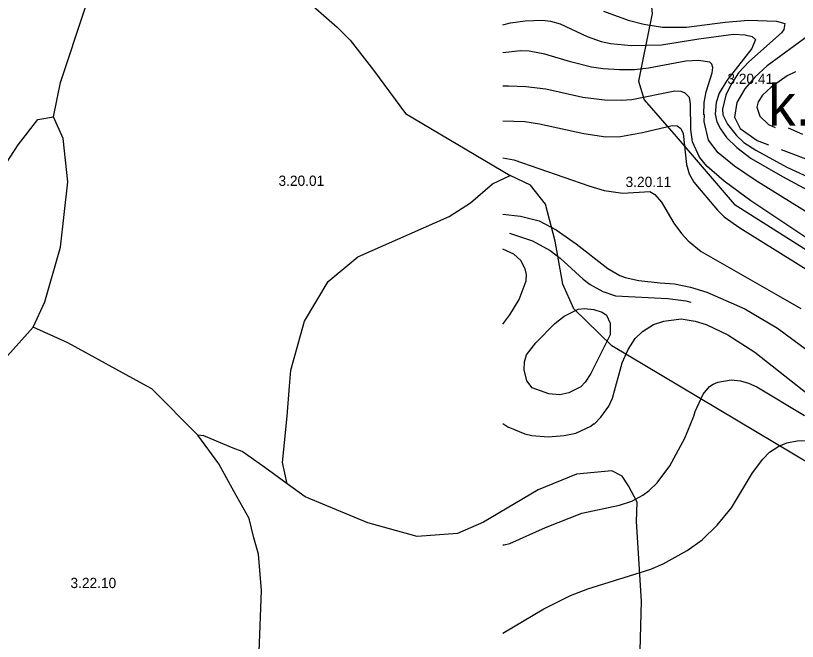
# Model space of a CAD drawing. Extents: x -662500 to -653478, y -1056827 to -1049993.
# Drawn here: x -661949 to -661377, y -1052187 to -1051729 of the extents above; entities that cross this region are included whole.
import ezdxf

# ---------------------------------------------------------------- set-up
doc = ezdxf.new("R2010")
doc.units = 0
for name, color, linetype in [('58', 7, 'Continuous'), ('Vrstva 24', 7, 'Continuous'), ('Vrstva 7', 7, 'Continuous')]:
    doc.layers.add(name, color=color, linetype=linetype)

msp = doc.modelspace()

# ---------------------------------------------------------------- linework, layer by layer
at = {"layer": 'Vrstva 24'}
for points in [[(-661490, -1051648), (-661487.5, -1051669), (-661486.5, -1051694), (-661483, -1051727.5), (-661490.5, -1051763.5), (-661493, -1051777), (-661489, -1051790.5), (-661465.5, -1051817.5), (-661423, -1051867), (-661344, -1051917)], [(-661921, -1051803), (-661916, -1051778), (-661898, -1051723.5), (-661882, -1051673)], [(-661882, -1051673), (-661865.5, -1051680), (-661808.5, -1051691), (-661771.5, -1051702.5), (-661762, -1051705), (-661744, -1051714.5), (-661731, -1051722), (-661713.5, -1051737.5), (-661704, -1051747), (-661687, -1051769), (-661663.5, -1051800.5), (-661587, -1051846)], [(-662096, -1051971), (-662093, -1051958.5), (-662081.5, -1051931.5), (-662066.5, -1051913.5), (-661997.5, -1051871.5), (-661971, -1051851), (-661958.5, -1051841.5), (-661947, -1051823.5), (-661932.5, -1051805), (-661921, -1051803)], [(-661936, -1051957), (-661927.5, -1051938.5), (-661916, -1051898.5), (-661910.5, -1051850.5), (-661914, -1051819), (-661921, -1051803)], [(-661750, -1052071.5), (-661753.5, -1052056), (-661750, -1052022), (-661748.36, -1052000), (-661747.5, -1051988.5), (-661737.5, -1051952.5), (-661720, -1051923.5), (-661698.5, -1051905.5), (-661631.5, -1051876), (-661616, -1051866), (-661600, -1051852), (-661587, -1051846)], [(-661191, -1052048), (-661295, -1052071.5), (-661327.5, -1052073.5), (-661352, -1052066.5), (-661463.18, -1052000), (-661512.5, -1051970.5), (-661540.5, -1051943.5), (-661548.5, -1051925.5), (-661554, -1051894), (-661561, -1051867), (-661572, -1051853), (-661587, -1051846)], [(-661794, -1052312.5), (-661840, -1052307.5), (-661898, -1052305.5), (-661929.5, -1052300.5), (-661957, -1052291.5), (-661974.5, -1052281), (-662001, -1052255), (-662045.5, -1052192), (-662051, -1052169.5), (-662044.5, -1052124.5), (-662027, -1052066), (-662005.5, -1052025.5), (-661977.17, -1052000), (-661965.5, -1051989.5), (-661936, -1051957)], [(-661815.5, -1052036), (-661849, -1052002), (-661852.67, -1052000), (-661910.5, -1051968.5), (-661936, -1051957)], [(-661794, -1052312.5), (-661770.5, -1052194.5), (-661769, -1052149.5), (-661771, -1052123), (-661774.5, -1052111), (-661778, -1052097), (-661789, -1052077.5), (-661800, -1052057), (-661815.5, -1052036)], [(-661750, -1052071.5), (-661766.5, -1052059.5), (-661783, -1052048), (-661789.5, -1052045.5), (-661811, -1052036.5), (-661815.5, -1052036)], [(-661493, -1052317.5), (-661495, -1052310.5), (-661491, -1052157.5), (-661494.5, -1052099), (-661494, -1052085), (-661500.5, -1052073), (-661505, -1052066), (-661512.5, -1052062), (-661538.5, -1052064.5), (-661566.5, -1052076), (-661606.5, -1052099.5), (-661625.5, -1052108), (-661655, -1052110), (-661691, -1052100), (-661737, -1052081), (-661750, -1052071.5)]]:
    msp.add_lwpolyline(points, dxfattribs=at)
at = {"layer": 'Vrstva 7'}
for p, q in [((-661518.72, -1051725.73), (-661500.58, -1051732.39)), ((-661518.72, -1051725.73), (-661500.58, -1051732.39)), ((-661592.25, -1051735.65), (-661586.74, -1051734.38)), ((-661592.25, -1051735.65), (-661586.74, -1051734.38)), ((-661586.74, -1051734.38), (-661575.97, -1051732.82)), ((-661586.74, -1051734.38), (-661575.97, -1051732.82)), ((-661575.97, -1051732.82), (-661563.22, -1051732.25)), ((-661575.97, -1051732.82), (-661563.22, -1051732.25)), ((-661563.22, -1051732.25), (-661557.55, -1051732.96)), ((-661563.22, -1051732.25), (-661557.55, -1051732.96)), ((-661557.55, -1051732.96), (-661550.46, -1051735.08)), ((-661557.55, -1051732.96), (-661550.46, -1051735.08)), ((-661550.46, -1051735.08), (-661530.62, -1051744.3)), ((-661550.46, -1051735.08), (-661530.62, -1051744.3)), ((-661500.58, -1051732.39), (-661489.24, -1051735.23)), ((-661500.58, -1051732.39), (-661489.24, -1051735.23)), ((-661489.24, -1051735.23), (-661475.64, -1051737.35)), ((-661489.24, -1051735.23), (-661475.64, -1051737.35)), ((-661458.07, -1051737.35), (-661429.72, -1051733.67)), ((-661458.07, -1051737.35), (-661429.72, -1051733.67)), ((-661429.72, -1051733.67), (-661412.72, -1051732.39)), ((-661429.72, -1051733.67), (-661412.72, -1051732.39)), ((-661412.72, -1051732.39), (-661392.03, -1051733.1)), ((-661412.72, -1051732.39), (-661392.03, -1051733.1)), ((-661392.03, -1051733.1), (-661385.93, -1051734.66)), ((-661392.03, -1051733.1), (-661385.93, -1051734.66)), ((-661385.93, -1051734.66), (-661386.78, -1051739.05)), ((-661385.93, -1051734.66), (-661386.78, -1051739.05)), ((-661475.64, -1051737.35), (-661458.07, -1051737.35)), ((-661475.64, -1051737.35), (-661458.07, -1051737.35)), ((-661448.99, -1051745.85), (-661423.49, -1051742.6)), ((-661448.99, -1051745.85), (-661423.49, -1051742.6)), ((-661423.49, -1051742.6), (-661414.98, -1051743.02)), ((-661423.49, -1051742.6), (-661414.98, -1051743.02)), ((-661388.48, -1051741.46), (-661412.43, -1051762.72)), ((-661388.48, -1051741.46), (-661412.43, -1051762.72)), ((-661386.78, -1051739.05), (-661388.48, -1051741.46)), ((-661386.78, -1051739.05), (-661388.48, -1051741.46)), ((-661530.62, -1051744.3), (-661520.42, -1051747.84)), ((-661530.62, -1051744.3), (-661520.42, -1051747.84)), ((-661520.42, -1051747.84), (-661513.62, -1051749.4)), ((-661520.42, -1051747.84), (-661513.62, -1051749.4)), ((-661476.2, -1051750.25), (-661448.99, -1051745.85)), ((-661476.2, -1051750.25), (-661448.99, -1051745.85)), ((-661414.98, -1051743.02), (-661409.88, -1051744.3)), ((-661414.98, -1051743.02), (-661409.88, -1051744.3)), ((-661407.47, -1051746.42), (-661410.17, -1051753.08)), ((-661407.47, -1051746.42), (-661410.17, -1051753.08)), ((-661409.88, -1051744.3), (-661407.47, -1051746.42)), ((-661409.88, -1051744.3), (-661407.47, -1051746.42)), ((-661368.97, -1051743.8), (-661398.97, -1051765.84)), ((-661513.62, -1051749.4), (-661498.31, -1051750.96)), ((-661513.62, -1051749.4), (-661498.31, -1051750.96)), ((-661498.31, -1051750.96), (-661476.2, -1051750.25)), ((-661498.31, -1051750.96), (-661476.2, -1051750.25)), ((-661410.17, -1051753.08), (-661428.45, -1051776.47)), ((-661410.17, -1051753.08), (-661428.45, -1051776.47)), ((-661579.37, -1051754.64), (-661592.25, -1051756.19)), ((-661573.14, -1051755.07), (-661579.37, -1051754.64)), ((-661561.52, -1051757.19), (-661573.14, -1051755.07)), ((-661542.81, -1051762.86), (-661561.52, -1051757.19)), ((-661527.51, -1051766.69), (-661542.81, -1051762.86)), ((-661458.35, -1051762.29), (-661485.84, -1051767.54)), ((-661449.28, -1051761.87), (-661458.35, -1051762.29)), ((-661440.78, -1051763.15), (-661449.28, -1051761.87)), ((-661439.5, -1051764.56), (-661440.78, -1051763.15)), ((-661438.79, -1051766.83), (-661439.5, -1051764.56)), ((-661412.43, -1051762.72), (-661419.94, -1051770.94)), ((-661412.43, -1051762.72), (-661419.94, -1051770.94)), ((-661398.97, -1051765.84), (-661407.9, -1051773.92)), ((-661519, -1051767.96), (-661527.51, -1051766.69)), ((-661507.1, -1051768.67), (-661519, -1051767.96)), ((-661496.05, -1051768.53), (-661507.1, -1051768.67)), ((-661485.84, -1051767.54), (-661496.05, -1051768.53)), ((-661443.47, -1051784.69), (-661439.08, -1051770.8)), ((-661439.08, -1051770.8), (-661438.79, -1051766.83)), ((-661419.94, -1051770.94), (-661425.61, -1051779.58)), ((-661419.94, -1051770.94), (-661425.61, -1051779.58)), ((-661378.28, -1051770.23), (-661384.37, -1051772.92)), ((-661428.45, -1051776.47), (-661433.97, -1051785.82)), ((-661428.45, -1051776.47), (-661433.97, -1051785.82)), ((-661407.9, -1051773.92), (-661415.41, -1051782.56)), ((-661384.37, -1051772.92), (-661396.14, -1051781.43)), ((-661588.16, -1051780.58), (-661592.25, -1051780.7)), ((-661575.41, -1051781.14), (-661588.16, -1051780.58)), ((-661560.95, -1051782.84), (-661575.41, -1051781.14)), ((-661533.74, -1051788.79), (-661560.95, -1051782.84)), ((-661425.61, -1051779.58), (-661429.16, -1051787.24)), ((-661425.61, -1051779.58), (-661429.16, -1051787.24)), ((-661415.41, -1051782.56), (-661421.22, -1051792.48)), ((-661396.14, -1051781.43), (-661402.37, -1051787.09)), ((-661466.57, -1051784.26), (-661498.03, -1051790.5)), ((-661461.75, -1051784.54), (-661466.57, -1051784.26)), ((-661458.92, -1051785.68), (-661461.75, -1051784.54)), ((-661455.8, -1051788.8), (-661458.92, -1051785.68)), ((-661445.03, -1051792.62), (-661443.47, -1051784.69)), ((-661433.97, -1051785.82), (-661436.38, -1051792.62)), ((-661433.97, -1051785.82), (-661436.38, -1051792.62)), ((-661429.16, -1051787.24), (-661431.71, -1051797.44)), ((-661429.16, -1051787.24), (-661431.71, -1051797.44)), ((-661402.37, -1051787.09), (-661405.63, -1051792.05)), ((-661517.87, -1051790.92), (-661533.74, -1051788.79)), ((-661505.68, -1051791.06), (-661517.87, -1051790.92)), ((-661498.03, -1051790.5), (-661505.68, -1051791.06)), ((-661455.09, -1051793.47), (-661455.8, -1051788.8)), ((-661454.81, -1051812.18), (-661455.09, -1051793.47)), ((-661445.31, -1051801.69), (-661445.03, -1051792.62)), ((-661436.38, -1051792.62), (-661436.95, -1051801.12)), ((-661436.38, -1051792.62), (-661436.95, -1051801.12)), ((-661421.22, -1051792.48), (-661422.92, -1051803.25)), ((-661405.63, -1051792.05), (-661406.48, -1051796.02)), ((-661431.71, -1051797.44), (-661431.28, -1051801.69)), ((-661431.71, -1051797.44), (-661431.28, -1051801.69)), ((-661406.48, -1051796.02), (-661404.35, -1051802.54)), ((-661444.74, -1051801.69), (-661445.31, -1051801.69)), ((-661445.03, -1051806.51), (-661444.74, -1051801.69)), ((-661436.95, -1051801.12), (-661435.67, -1051806.79)), ((-661436.95, -1051801.12), (-661435.67, -1051806.79)), ((-661431.28, -1051801.69), (-661428.02, -1051808.49)), ((-661431.28, -1051801.69), (-661428.02, -1051808.49)), ((-661422.92, -1051803.25), (-661418.81, -1051811.61)), ((-661404.35, -1051802.54), (-661397.91, -1051808.56)), ((-661592.25, -1051805.95), (-661576.26, -1051806.51)), ((-661576.26, -1051806.51), (-661565.49, -1051808.21)), ((-661565.49, -1051808.21), (-661533.18, -1051815.3)), ((-661490.09, -1051814.59), (-661468.55, -1051809.34)), ((-661468.55, -1051809.34), (-661464.87, -1051809.72)), ((-661464.87, -1051809.72), (-661462.18, -1051811.61)), ((-661441.77, -1051820.11), (-661445.03, -1051806.51)), ((-661435.67, -1051806.79), (-661433.12, -1051811.75)), ((-661435.67, -1051806.79), (-661433.12, -1051811.75)), ((-661428.02, -1051808.49), (-661421.5, -1051816.57)), ((-661428.02, -1051808.49), (-661421.5, -1051816.57)), ((-661397.91, -1051808.56), (-661393.16, -1051810.9)), ((-661372.75, -1051816.01), (-661383.33, -1051811.28)), ((-661533.18, -1051815.3), (-661517.02, -1051817.56)), ((-661506.25, -1051817.42), (-661490.09, -1051814.59)), ((-661462.18, -1051811.61), (-661460.47, -1051815.3)), ((-661460.47, -1051815.3), (-661458.07, -1051837.97)), ((-661453.53, -1051821.25), (-661454.81, -1051812.18)), ((-661433.12, -1051811.75), (-661428.59, -1051818.27)), ((-661433.12, -1051811.75), (-661428.59, -1051818.27)), ((-661421.5, -1051816.57), (-661415.97, -1051821.81)), ((-661421.5, -1051816.57), (-661415.97, -1051821.81)), ((-661418.81, -1051811.61), (-661406.2, -1051820.26)), ((-661517.02, -1051817.56), (-661506.25, -1051817.42)), ((-661448.43, -1051832.59), (-661453.53, -1051821.25)), ((-661434.82, -1051829.47), (-661441.77, -1051820.11)), ((-661428.59, -1051818.27), (-661421.22, -1051825.36)), ((-661428.59, -1051818.27), (-661421.22, -1051825.36)), ((-661415.97, -1051821.81), (-661407.33, -1051827.48)), ((-661415.97, -1051821.81), (-661407.33, -1051827.48)), ((-661406.2, -1051820.26), (-661397.96, -1051823.42)), ((-661421.22, -1051825.36), (-661410.73, -1051833.58)), ((-661421.22, -1051825.36), (-661410.73, -1051833.58)), ((-661407.33, -1051827.48), (-661384.66, -1051839.81)), ((-661407.33, -1051827.48), (-661384.66, -1051839.81)), ((-661332.79, -1051848.46), (-661388.36, -1051827.11)), ((-661592.25, -1051832.94), (-661584.19, -1051834.57)), ((-661443.19, -1051839.1), (-661448.43, -1051832.59)), ((-661422.78, -1051839.1), (-661434.82, -1051829.47)), ((-661410.73, -1051833.58), (-661387.77, -1051846.76)), ((-661410.73, -1051833.58), (-661387.77, -1051846.76)), ((-661584.19, -1051834.57), (-661529.49, -1051853.56)), ((-661458.07, -1051837.97), (-661455.94, -1051844.63)), ((-661430.29, -1051850.02), (-661443.19, -1051839.1)), ((-661406.91, -1051849.88), (-661422.78, -1051839.1)), ((-661384.66, -1051839.81), (-661357.45, -1051852.28)), ((-661384.66, -1051839.81), (-661357.45, -1051852.28)), ((-661455.94, -1051844.63), (-661452.68, -1051850.87)), ((-661452.68, -1051850.87), (-661435.39, -1051871.27)), ((-661411.02, -1051864.47), (-661430.29, -1051850.02)), ((-661352.06, -1051883.89), (-661406.91, -1051849.88)), ((-661387.77, -1051846.76), (-661345.26, -1051869.86)), ((-661387.77, -1051846.76), (-661345.26, -1051869.86)), ((-661529.49, -1051853.56), (-661518.15, -1051856.96)), ((-661518.15, -1051856.96), (-661504.55, -1051858.8)), ((-661504.55, -1051858.8), (-661484.85, -1051857.67)), ((-661484.85, -1051857.67), (-661481.17, -1051859.94)), ((-661481.17, -1051859.94), (-661476.35, -1051865.46)), ((-661476.35, -1051865.46), (-661467.14, -1051880.77)), ((-661360, -1051898.63), (-661411.02, -1051864.47)), ((-661592.25, -1051874.24), (-661579.37, -1051875.67)), ((-661435.39, -1051871.27), (-661430.29, -1051876.09)), ((-661579.37, -1051875.67), (-661565.77, -1051879.07)), ((-661565.77, -1051879.07), (-661553.3, -1051885.73)), ((-661430.29, -1051876.09), (-661418.95, -1051884.31)), ((-661553.3, -1051885.73), (-661538.7, -1051895.93)), ((-661467.14, -1051880.77), (-661461.61, -1051888.42)), ((-661418.95, -1051884.31), (-661362.97, -1051919.17)), ((-661587.45, -1051888.14), (-661570.59, -1051893.81)), ((-661461.61, -1051888.42), (-661456.65, -1051893.81)), ((-661570.59, -1051893.81), (-661557.69, -1051900.89)), ((-661538.7, -1051895.93), (-661515.46, -1051914.07)), ((-661456.65, -1051893.81), (-661447.15, -1051901.6)), ((-661584.33, -1051903.44), (-661592.25, -1051899.84)), ((-661557.69, -1051900.89), (-661550.32, -1051906.42)), ((-661447.15, -1051901.6), (-661392.53, -1051932.69)), ((-661579.23, -1051908.26), (-661584.33, -1051903.44)), ((-661575.97, -1051914.22), (-661579.23, -1051908.26)), ((-661550.32, -1051906.42), (-661533.46, -1051921.87)), ((-661574.98, -1051918.47), (-661575.97, -1051914.22)), ((-661515.46, -1051914.07), (-661506.82, -1051919.03)), ((-661575.26, -1051923), (-661574.98, -1051918.47)), ((-661506.82, -1051919.03), (-661502.85, -1051920.59)), ((-661580.37, -1051936.61), (-661575.26, -1051923)), ((-661533.46, -1051921.87), (-661528.5, -1051925.69)), ((-661528.5, -1051925.69), (-661519.15, -1051930.94)), ((-661502.85, -1051920.59), (-661492.93, -1051922.72)), ((-661492.93, -1051922.72), (-661477.34, -1051924.56)), ((-661477.34, -1051924.56), (-661466.85, -1051925.13)), ((-661466.85, -1051925.13), (-661454.95, -1051927.54)), ((-661519.15, -1051930.94), (-661509.93, -1051933.91)), ((-661454.95, -1051927.54), (-661443.04, -1051931.22)), ((-661443.04, -1051931.22), (-661415.27, -1051943.41)), ((-661587.17, -1051947.94), (-661580.37, -1051936.61)), ((-661509.93, -1051933.91), (-661471.67, -1051935.9)), ((-661471.67, -1051935.9), (-661458.35, -1051937.6)), ((-661392.53, -1051932.69), (-661374.39, -1051943.32)), ((-661458.35, -1051937.6), (-661454.81, -1051938.59)), ((-661592.25, -1051954.82), (-661587.17, -1051947.94)), ((-661547.35, -1051948.94), (-661537.28, -1051943.69)), ((-661537.28, -1051943.69), (-661532.61, -1051943.27)), ((-661532.61, -1051943.27), (-661525.81, -1051943.98)), ((-661525.81, -1051943.98), (-661519.57, -1051945.96)), ((-661519.57, -1051945.96), (-661516.45, -1051948.08)), ((-661516.45, -1051948.08), (-661513.9, -1051953.9)), ((-661415.27, -1051943.41), (-661391.46, -1051957.72)), ((-661568.18, -1051968.35), (-661554.29, -1051954.32)), ((-661554.29, -1051954.32), (-661547.35, -1051948.94)), ((-661513.9, -1051953.9), (-661513.93, -1051962.45)), ((-661482.16, -1051954.89), (-661474.5, -1051952.48)), ((-661482.16, -1051954.89), (-661474.5, -1051952.48)), ((-661474.5, -1051952.48), (-661461.75, -1051950.92)), ((-661474.5, -1051952.48), (-661461.75, -1051950.92)), ((-661461.75, -1051950.92), (-661451.55, -1051952.48)), ((-661461.75, -1051950.92), (-661451.55, -1051952.48)), ((-661451.55, -1051952.48), (-661443.61, -1051954.89)), ((-661451.55, -1051952.48), (-661443.61, -1051954.89)), ((-661495.48, -1051965.23), (-661490.09, -1051959.99)), ((-661495.48, -1051965.23), (-661490.09, -1051959.99)), ((-661490.09, -1051959.99), (-661482.16, -1051954.89)), ((-661490.09, -1051959.99), (-661482.16, -1051954.89)), ((-661443.61, -1051954.89), (-661427.74, -1051962.54)), ((-661443.61, -1051954.89), (-661427.74, -1051962.54)), ((-661391.46, -1051957.72), (-661348.66, -1051989.18)), ((-661513.93, -1051962.45), (-661527.93, -1051990.74)), ((-661500.58, -1051973.17), (-661495.48, -1051965.23)), ((-661500.58, -1051973.17), (-661495.48, -1051965.23)), ((-661427.74, -1051962.54), (-661407.9, -1051975.29)), ((-661427.74, -1051962.54), (-661407.9, -1051975.29)), ((-661574.98, -1051977.14), (-661568.18, -1051968.35)), ((-661576.51, -1051982.27), (-661574.98, -1051977.14)), ((-661504.97, -1051983.09), (-661500.58, -1051973.17)), ((-661504.97, -1051983.09), (-661500.58, -1051973.17)), ((-661407.9, -1051975.29), (-661368.78, -1052006.19)), ((-661407.9, -1051975.29), (-661368.78, -1052006.19)), ((-661576.82, -1051988.19), (-661576.51, -1051982.27)), ((-661512.06, -1052008.88), (-661504.97, -1051983.09)), ((-661512.06, -1052008.88), (-661504.97, -1051983.09)), ((-661574.7, -1051996.13), (-661576.82, -1051988.19)), ((-661527.93, -1051990.74), (-661532.18, -1051997.12)), ((-661570.87, -1052001.37), (-661574.7, -1051996.13)), ((-661532.18, -1051997.12), (-661535.3, -1052000.52)), ((-661441.2, -1052000.38), (-661438.51, -1051998.54)), ((-661438.51, -1051998.54), (-661435.11, -1051997.26)), ((-661435.11, -1051997.26), (-661425.19, -1051995.56)), ((-661425.19, -1051995.56), (-661418.39, -1051996.27)), ((-661418.39, -1051996.27), (-661412.72, -1051997.83)), ((-661412.72, -1051997.83), (-661406.62, -1052000.66)), ((-661558.68, -1052005.62), (-661570.87, -1052001.37)), ((-661550.61, -1052006.33), (-661558.68, -1052005.62)), ((-661544.07, -1052005.04), (-661550.61, -1052006.33)), ((-661535.3, -1052000.52), (-661544.07, -1052005.04)), ((-661451.69, -1052018.52), (-661445.88, -1052006.05)), ((-661445.88, -1052006.05), (-661441.2, -1052000.38)), ((-661406.62, -1052000.66), (-661371.62, -1052021.64)), ((-661514.75, -1052014.83), (-661512.06, -1052008.88)), ((-661514.75, -1052014.83), (-661512.06, -1052008.88)), ((-661520.56, -1052022.77), (-661514.75, -1052014.83)), ((-661520.56, -1052022.77), (-661514.75, -1052014.83)), ((-661525.38, -1052027.59), (-661520.56, -1052022.77)), ((-661525.38, -1052027.59), (-661520.56, -1052022.77)), ((-661459.2, -1052038.07), (-661452.54, -1052021.92)), ((-661452.54, -1052021.92), (-661451.69, -1052018.52)), ((-661592.25, -1052027.48), (-661588.73, -1052029.85)), ((-661592.25, -1052027.48), (-661588.73, -1052029.85)), ((-661528.07, -1052029.43), (-661526.09, -1052027.59)), ((-661528.07, -1052029.43), (-661526.09, -1052027.59)), ((-661526.09, -1052027.59), (-661525.38, -1052027.59)), ((-661526.09, -1052027.59), (-661525.38, -1052027.59)), ((-661588.73, -1052029.85), (-661576.26, -1052034.96)), ((-661588.73, -1052029.85), (-661576.26, -1052034.96)), ((-661547.35, -1052036.23), (-661538.84, -1052034.39)), ((-661547.35, -1052036.23), (-661538.84, -1052034.39)), ((-661538.84, -1052034.39), (-661528.07, -1052029.43)), ((-661538.84, -1052034.39), (-661528.07, -1052029.43)), ((-661576.26, -1052034.96), (-661571.16, -1052036.23)), ((-661576.26, -1052034.96), (-661571.16, -1052036.23)), ((-661571.16, -1052036.23), (-661559.25, -1052037.22)), ((-661571.16, -1052036.23), (-661559.25, -1052037.22)), ((-661559.25, -1052037.22), (-661547.35, -1052036.23)), ((-661559.25, -1052037.22), (-661547.35, -1052036.23)), ((-661470.11, -1052058.48), (-661459.2, -1052038.07)), ((-661384.66, -1052041.62), (-661377, -1052040.2)), ((-661377, -1052040.2), (-661366.8, -1052039.77)), ((-661397.27, -1052048.42), (-661390.33, -1052044.03)), ((-661390.33, -1052044.03), (-661384.66, -1052041.62)), ((-661402.23, -1052053.38), (-661397.27, -1052048.42)), ((-661409.74, -1052063.58), (-661402.23, -1052053.38)), ((-661479.46, -1052070.81), (-661470.11, -1052058.48)), ((-661425.05, -1052089.09), (-661409.74, -1052063.58)), ((-661485.28, -1052076.48), (-661479.46, -1052070.81)), ((-661498.03, -1052084.13), (-661489.81, -1052079.88)), ((-661489.81, -1052079.88), (-661485.28, -1052076.48)), ((-661507.1, -1052087.11), (-661498.03, -1052084.13)), ((-661534.59, -1052093.06), (-661507.1, -1052087.11)), ((-661435.53, -1052101.85), (-661425.05, -1052089.09)), ((-661561.09, -1052103.41), (-661534.59, -1052093.06)), ((-661446.44, -1052112.48), (-661435.53, -1052101.85)), ((-661587.31, -1052115.17), (-661561.09, -1052103.41)), ((-661457.5, -1052120.41), (-661446.44, -1052112.48)), ((-661592.25, -1052116.21), (-661591.42, -1052116.16)), ((-661591.42, -1052116.16), (-661587.31, -1052115.17)), ((-661475.07, -1052130.05), (-661457.5, -1052120.41)), ((-661484.14, -1052134.02), (-661475.07, -1052130.05)), ((-661530.06, -1052148.47), (-661484.14, -1052134.02)), ((-661542.81, -1052153.29), (-661530.06, -1052148.47)), ((-661562.37, -1052162.93), (-661542.81, -1052153.29)), ((-661592.25, -1052180.9), (-661562.37, -1052162.93))]:
    msp.add_line(p, q, dxfattribs=at)

# ---------------------------------------------------------------- texts
at = {"layer": '58'}
msp.add_text('k.ú. Žáravice', height=30, dxfattribs=at).set_placement((-661398.23, -1051809.48))
at = {"layer": 'Vrstva 24'}
for s, p in [('3.20.41', (-661428.05, -1051778.96)), ('3.20.01', (-661756.45, -1051853.54)), ('3.20.11', (-661502.53, -1051854.39)), ('3.22.10', (-661908.63, -1052147.81))]:
    msp.add_text(s, height=7.5, dxfattribs=at).set_placement(p)

doc.saveas('drawing.dxf')
